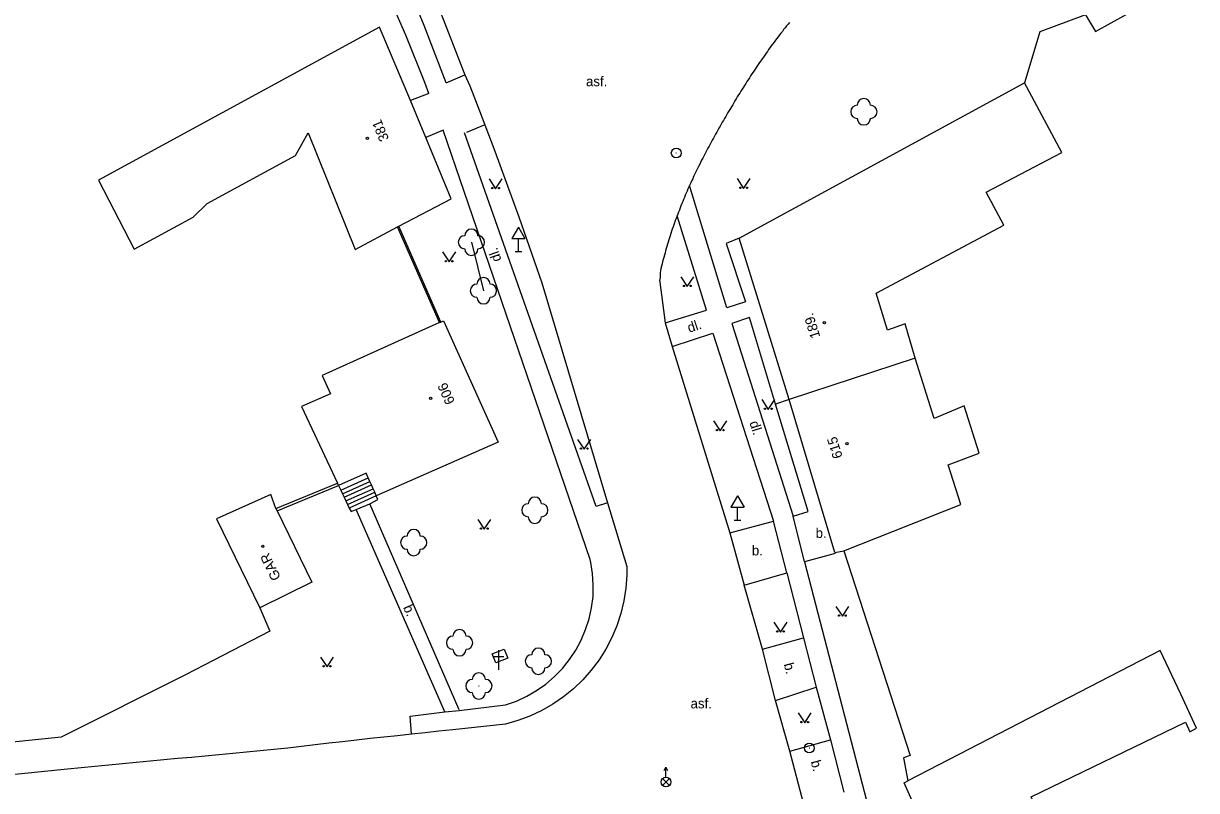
# Model space of a CAD drawing. Extents: x -545714 to -535419, y -1201788 to -1194297.
# Drawn here: x -535590.1 to -535501, y -1201602.5 to -1201544.3 of the extents above; entities that cross this region are included whole.
import ezdxf

# ---------------------------------------------------------------- set-up
doc = ezdxf.new("R2010")
doc.units = 0
for name, color, linetype in [('Vrstva 1', 7, 'Continuous'), ('Vrstva 10', 7, 'Continuous'), ('Vrstva 11', 7, 'Continuous'), ('Vrstva 12', 7, 'Continuous'), ('Vrstva 15', 7, 'Continuous'), ('Vrstva 2', 7, 'Continuous'), ('Vrstva 3', 7, 'Continuous'), ('Vrstva 4', 7, 'Continuous'), ('Vrstva 5', 7, 'Continuous'), ('Vrstva 8', 7, 'Continuous'), ('Vrstva 9', 7, 'Continuous')]:
    doc.layers.add(name, color=color, linetype=linetype)

msp = doc.modelspace()

# ---------------------------------------------------------------- linework, layer by layer
at = {"layer": 'Vrstva 1'}
for centre, radius in [((-535540.49, -1201554.1), 0.375), ((-535540.49, -1201554.1), 0.0005), ((-535530.38, -1201599.301), 0.375), ((-535530.38, -1201599.301), 0.0005)]:
    msp.add_circle(centre, radius, dxfattribs=at)
at = {"layer": 'Vrstva 10'}
for p, q in [((-535552.48, -1201559.724), (-535552.98, -1201560.59)), ((-535552.48, -1201559.724), (-535551.98, -1201560.59)), ((-535552.98, -1201560.59), (-535551.98, -1201560.59)), ((-535552.48, -1201561.59), (-535552.48, -1201560.59)), ((-535552.73, -1201561.59), (-535552.23, -1201561.59)), ((-535535.84, -1201580.134), (-535536.34, -1201581)), ((-535535.84, -1201580.134), (-535535.34, -1201581)), ((-535536.34, -1201581), (-535535.34, -1201581)), ((-535535.84, -1201582), (-535535.84, -1201581)), ((-535536.09, -1201582), (-535535.59, -1201582))]:
    msp.add_line(p, q, dxfattribs=at)
for points in [[(-535509.4, -1201543.6), (-535512.88, -1201544.9), (-535514.03, -1201548.76)], [(-535558.47, -1201566.98), (-535561.66, -1201559.7)], [(-535558.38, -1201566.94), (-535561.57, -1201559.65)], [(-535570.89, -1201581.11), (-535566.22, -1201579.17)], [(-535570.81, -1201581.28), (-535566.14, -1201579.35)], [(-535527.76, -1201584.32), (-535522.72, -1201599.86), (-535523.22, -1201600.05), (-535522.9, -1201601.79)], [(-535572.12, -1201588.65), (-535571.35, -1201590.42), (-535577.76, -1201593.75), (-535587.2, -1201598.48), (-535604.18, -1201600.22)]]:
    msp.add_lwpolyline(points, dxfattribs=at)
at = {"layer": 'Vrstva 11'}
for points in [[(-535559.28, -1201549.57), (-535559.59, -1201548.75), (-535561.04, -1201545.16), (-535567.24, -1201530.99), (-535567.78, -1201529.85), (-535568.21, -1201528.88), (-535572, -1201520.91), (-535578.88, -1201508.46), (-535580.82, -1201505.2), (-535588.58, -1201492.55)], [(-535566.65, -1201524.99), (-535563.37, -1201531.99), (-535558.46, -1201543.26), (-535558.14, -1201544.05), (-535556.54, -1201548.16)], [(-535557.96, -1201548.78), (-535558.09, -1201548.43), (-535559.64, -1201544.42), (-535559.94, -1201543.67), (-535565.46, -1201531.02), (-535568.06, -1201525.62)], [(-535531.89, -1201544.19), (-535532, -1201544.32), (-535532.11, -1201544.45), (-535532.22, -1201544.59), (-535532.33, -1201544.72), (-535532.43, -1201544.86), (-535532.54, -1201544.99), (-535532.65, -1201545.13), (-535532.75, -1201545.27), (-535532.86, -1201545.4), (-535532.96, -1201545.54), (-535533.06, -1201545.68), (-535533.17, -1201545.82), (-535533.27, -1201545.96), (-535533.37, -1201546.1), (-535533.47, -1201546.24), (-535533.57, -1201546.38), (-535533.67, -1201546.52), (-535533.77, -1201546.67), (-535533.87, -1201546.81), (-535533.97, -1201546.95), (-535534.07, -1201547.09), (-535534.16, -1201547.23), (-535534.26, -1201547.38), (-535534.36, -1201547.52), (-535534.45, -1201547.66), (-535534.55, -1201547.81), (-535534.65, -1201547.95), (-535534.74, -1201548.09), (-535534.84, -1201548.24), (-535534.93, -1201548.38), (-535535.02, -1201548.53), (-535535.12, -1201548.67), (-535535.21, -1201548.82), (-535535.3, -1201548.96), (-535535.39, -1201549.11), (-535535.49, -1201549.25), (-535535.58, -1201549.4), (-535535.67, -1201549.55), (-535535.76, -1201549.69)], [(-535557.96, -1201548.78), (-535556.54, -1201548.16)], [(-535556.54, -1201548.16), (-535556.17, -1201548.99), (-535555.44, -1201550.89)], [(-535559.28, -1201549.57), (-535560.67, -1201550.12)], [(-535535.76, -1201549.69), (-535535.85, -1201549.84), (-535535.94, -1201549.99), (-535536.03, -1201550.14), (-535536.12, -1201550.28), (-535536.2, -1201550.43), (-535536.29, -1201550.58), (-535536.38, -1201550.73), (-535536.47, -1201550.88), (-535536.56, -1201551.02), (-535536.64, -1201551.17), (-535536.73, -1201551.32), (-535536.82, -1201551.47), (-535536.9, -1201551.62), (-535536.99, -1201551.77), (-535537.07, -1201551.92), (-535537.16, -1201552.07), (-535537.25, -1201552.22), (-535537.33, -1201552.37), (-535537.41, -1201552.52), (-535537.5, -1201552.67), (-535537.58, -1201552.83), (-535537.67, -1201552.98), (-535537.75, -1201553.13), (-535537.83, -1201553.28), (-535537.91, -1201553.43), (-535538, -1201553.58), (-535538.08, -1201553.74), (-535538.16, -1201553.89), (-535538.24, -1201554.04), (-535538.32, -1201554.19), (-535538.4, -1201554.35), (-535538.48, -1201554.5), (-535538.56, -1201554.65), (-535538.64, -1201554.81), (-535538.71, -1201554.96), (-535538.79, -1201555.12), (-535538.87, -1201555.27), (-535538.94, -1201555.42), (-535539.02, -1201555.58), (-535539.09, -1201555.73), (-535539.17, -1201555.89), (-535539.24, -1201556.05), (-535539.31, -1201556.2), (-535539.39, -1201556.36), (-535539.46, -1201556.51), (-535539.49, -1201556.58)], [(-535555.44, -1201550.89), (-535555.04, -1201551.97)], [(-535555.04, -1201551.97), (-535556.43, -1201552.53)], [(-535555.04, -1201551.97), (-535554.27, -1201553.96), (-535552.45, -1201558.95), (-535550.71, -1201563.97), (-535545.7, -1201580.68)], [(-535558.19, -1201552.37), (-535559.5, -1201552.92)], [(-535556.97, -1201596.44), (-535553.45, -1201596.02), (-535552.63, -1201595.73), (-535551.85, -1201595.37), (-535551.1, -1201594.94), (-535550.39, -1201594.44), (-535549.74, -1201593.88), (-535549.13, -1201593.26), (-535548.59, -1201592.58), (-535548.11, -1201591.86), (-535547.7, -1201591.1), (-535547.37, -1201590.31), (-535547.11, -1201589.48), (-535546.92, -1201588.64), (-535546.81, -1201587.78), (-535546.79, -1201586.91), (-535546.84, -1201586.05), (-535546.98, -1201585.2), (-535547.02, -1201584.99), (-535558.19, -1201552.37)], [(-535545.7, -1201580.68), (-535546.57, -1201580.96), (-535556.56, -1201552.58)], [(-535539.49, -1201556.58), (-535539.53, -1201556.67), (-535539.6, -1201556.83), (-535539.67, -1201556.99), (-535539.74, -1201557.15), (-535539.81, -1201557.31), (-535539.87, -1201557.47), (-535539.94, -1201557.62), (-535540, -1201557.78), (-535540.07, -1201557.94), (-535540.13, -1201558.11), (-535540.19, -1201558.26), (-535540.25, -1201558.43), (-535540.31, -1201558.59), (-535540.38, -1201558.75), (-535540.43, -1201558.87)], [(-535536.64, -1201565.86), (-535539.49, -1201556.58)], [(-535540.43, -1201558.87), (-535540.5, -1201559.07), (-535540.56, -1201559.24), (-535540.62, -1201559.4), (-535540.67, -1201559.56), (-535540.73, -1201559.72), (-535540.79, -1201559.89), (-535540.84, -1201560.05), (-535540.89, -1201560.21), (-535540.95, -1201560.38), (-535541, -1201560.54), (-535541.05, -1201560.7), (-535541.1, -1201560.87), (-535541.15, -1201561.03), (-535541.2, -1201561.2), (-535541.25, -1201561.36), (-535541.3, -1201561.53), (-535541.34, -1201561.69), (-535541.39, -1201561.86), (-535541.44, -1201562.03), (-535541.48, -1201562.19), (-535541.53, -1201562.36), (-535541.57, -1201562.53), (-535541.61, -1201562.7), (-535541.66, -1201562.87), (-535541.69, -1201563.04), (-535541.71, -1201563.21), (-535541.72, -1201563.39), (-535541.72, -1201563.56), (-535541.75, -1201563.79), (-535541.73, -1201563.91)], [(-535538.2, -1201566.04), (-535540.43, -1201558.87)], [(-535535.71, -1201560.57), (-535536.7, -1201560.97), (-535535.22, -1201565.41), (-535536.64, -1201565.86)], [(-535541.73, -1201563.91), (-535541.33, -1201567.01)], [(-535541.33, -1201567.01), (-535538.2, -1201566.04)], [(-535541.33, -1201567.01), (-535540.8, -1201568.81)], [(-535532.94, -1201573.19), (-535534.92, -1201566.59), (-535536.26, -1201567.04), (-535531.61, -1201581.69)], [(-535540.8, -1201568.81), (-535537.7, -1201567.79)], [(-535537.7, -1201567.79), (-535533.09, -1201582.08)], [(-535540.8, -1201568.81), (-535536.43, -1201582.96)], [(-535531.9, -1201572.83), (-535532.94, -1201573.19)], [(-535531.61, -1201581.69), (-535530.48, -1201581.33), (-535532.94, -1201573.19)], [(-535565.97, -1201579.71), (-535563.88, -1201578.78)], [(-535566.14, -1201579.35), (-535565.97, -1201579.71)], [(-535565.97, -1201579.71), (-535565.84, -1201579.98)], [(-535565.84, -1201579.98), (-535563.76, -1201579.05)], [(-535565.71, -1201580.25), (-535563.64, -1201579.32)], [(-535565.58, -1201580.52), (-535563.51, -1201579.6)], [(-535565.84, -1201579.98), (-535565.71, -1201580.25)], [(-535565.71, -1201580.25), (-535565.58, -1201580.52)], [(-535565.58, -1201580.52), (-535565.45, -1201580.8)], [(-535565.45, -1201580.8), (-535563.39, -1201579.87)], [(-535563.27, -1201580.14), (-535565.32, -1201581.07)], [(-535565.32, -1201581.07), (-535565.19, -1201581.34), (-535564.79, -1201581.19), (-535563.76, -1201580.74), (-535563.15, -1201580.42), (-535563.27, -1201580.14)], [(-535556.98, -1201596.39), (-535563.76, -1201580.74)], [(-535545.7, -1201580.68), (-535544.25, -1201585.52), (-535544.25, -1201586.18), (-535544.32, -1201587.16), (-535544.47, -1201588.13), (-535544.7, -1201589.08), (-535545, -1201590.01), (-535545.38, -1201590.91), (-535545.83, -1201591.78), (-535546.35, -1201592.61), (-535546.94, -1201593.39), (-535547.59, -1201594.13), (-535548.3, -1201594.8), (-535549.06, -1201595.42), (-535549.86, -1201595.97), (-535550.71, -1201596.46), (-535551.6, -1201596.87), (-535552.52, -1201597.22), (-535553.46, -1201597.48), (-535557.47, -1201597.91), (-535558.52, -1201598.03), (-535559.56, -1201598.14), (-535560.61, -1201598.25)], [(-535565.45, -1201580.8), (-535565.32, -1201581.07)], [(-535558.07, -1201596.56), (-535564.79, -1201581.19)], [(-535536.43, -1201582.96), (-535533.09, -1201582.08)], [(-535532.08, -1201585.99), (-535533.09, -1201582.08)], [(-535530.74, -1201585.15), (-535531.61, -1201581.69)], [(-535536.43, -1201582.96), (-535535.33, -1201586.94)], [(-535528.42, -1201584.52), (-535530.74, -1201585.15)], [(-535530.74, -1201585.15), (-535525.02, -1201607.19), (-535521.43, -1201605.87)], [(-535535.33, -1201586.94), (-535532.08, -1201585.99)], [(-535532.08, -1201585.99), (-535530.82, -1201590.92)], [(-535533.95, -1201591.78), (-535535.33, -1201586.94)], [(-535533.95, -1201591.78), (-535530.82, -1201590.92)], [(-535530.82, -1201590.92), (-535529.85, -1201594.69)], [(-535554.19, -1201592.84), (-535554.46, -1201592.14), (-535553.56, -1201591.78), (-535553.29, -1201592.48), (-535554.19, -1201592.84)], [(-535532.94, -1201595.69), (-535533.95, -1201591.78)], [(-535532.94, -1201595.69), (-535529.85, -1201594.69)], [(-535529.85, -1201594.69), (-535528.76, -1201598.67)], [(-535531.87, -1201599.53), (-535532.94, -1201595.69)], [(-535560.61, -1201598.25), (-535560.69, -1201596.89), (-535558.07, -1201596.56)], [(-535558.07, -1201596.56), (-535556.97, -1201596.44)], [(-535560.61, -1201598.25), (-535561.65, -1201598.37), (-535562.7, -1201598.48), (-535563.74, -1201598.59), (-535564.78, -1201598.7), (-535565.83, -1201598.82), (-535566.87, -1201598.93), (-535567.92, -1201599.06), (-535568.96, -1201599.19), (-535570, -1201599.31), (-535571.05, -1201599.42), (-535572.09, -1201599.51), (-535573.14, -1201599.62), (-535574.18, -1201599.72), (-535575.23, -1201599.81), (-535576.27, -1201599.91), (-535577.32, -1201600.01), (-535578.37, -1201600.11), (-535579.41, -1201600.21), (-535580.46, -1201600.31), (-535581.5, -1201600.41), (-535582.55, -1201600.51), (-535583.59, -1201600.61), (-535584.64, -1201600.71), (-535585.68, -1201600.81), (-535586.73, -1201600.91), (-535601.96, -1201602.45)], [(-535531.87, -1201599.53), (-535528.76, -1201598.67)], [(-535528.76, -1201598.67), (-535527.76, -1201602.65)], [(-535530.83, -1201603.48), (-535531.87, -1201599.53)]]:
    msp.add_lwpolyline(points, dxfattribs=at)
at = {"layer": 'Vrstva 12'}
msp.add_lwpolyline([(-535556.05, -1201560.88), (-535555.13, -1201564.56)], dxfattribs=at)
for centre in [(-535526.24, -1201550.97), (-535556.05, -1201560.88), (-535555.13, -1201564.56), (-535551.23, -1201581.24), (-535560.43, -1201583.7), (-535556.95, -1201591.3), (-535550.96, -1201592.71), (-535555.48, -1201594.59)]:
    msp.add_circle(centre, 0.0005, dxfattribs=at)
for centre, start, end in [((-535526.24, -1201550.47), 0, 179.99999), ((-535526.74, -1201550.97), 89.99999, 269.99999), ((-535525.74, -1201550.97), 270, 89.99999), ((-535526.24, -1201551.47), 179.99999, 359.99999), ((-535556.05, -1201560.38), 0, 179.99999), ((-535556.55, -1201560.88), 89.99999, 269.99999), ((-535555.55, -1201560.88), 270, 89.99999), ((-535556.05, -1201561.38), 179.99999, 359.99999), ((-535555.13, -1201564.06), 0, 179.99999), ((-535555.63, -1201564.56), 89.99999, 269.99999), ((-535554.63, -1201564.56), 270, 89.99999), ((-535555.13, -1201565.06), 179.99999, 359.99999), ((-535551.73, -1201581.24), 89.99999, 269.99999), ((-535551.23, -1201580.74), 0, 179.99999), ((-535550.73, -1201581.24), 270, 89.99999), ((-535551.23, -1201581.74), 179.99999, 359.99999), ((-535560.93, -1201583.7), 89.99999, 269.99999), ((-535560.43, -1201583.2), 0, 179.99999), ((-535559.93, -1201583.7), 270, 89.99999), ((-535560.43, -1201584.2), 179.99999, 359.99999), ((-535556.95, -1201590.8), 0, 179.99999), ((-535557.45, -1201591.3), 89.99999, 269.99999), ((-535556.45, -1201591.3), 270, 89.99999), ((-535556.95, -1201591.8), 179.99999, 359.99999), ((-535551.46, -1201592.71), 89.99999, 269.99999), ((-535550.96, -1201592.21), 0, 179.99999), ((-535550.46, -1201592.71), 270, 89.99999), ((-535550.96, -1201593.21), 179.99999, 359.99999), ((-535555.98, -1201594.59), 89.99999, 269.99999), ((-535555.48, -1201594.09), 0, 179.99999), ((-535554.98, -1201594.59), 270, 89.99999), ((-535555.48, -1201595.09), 179.99999, 359.99999)]:
    msp.add_arc(centre, 0.5, start, end, dxfattribs=at)
at = {"layer": 'Vrstva 2'}
for p, q in [((-535541.27, -1201601.505), (-535541.27, -1201600.755)), ((-535541.535, -1201602.144), (-535541.006, -1201601.616)), ((-535541.006, -1201602.148), (-535541.535, -1201601.616))]:
    msp.add_line(p, q, dxfattribs=at)
msp.add_lwpolyline([(-535541.395, -1201601.005), (-535541.27, -1201600.755), (-535541.145, -1201601.005)], dxfattribs=at)
msp.add_circle((-535541.27, -1201601.88), 0.375, dxfattribs=at)
at = {"layer": 'Vrstva 3'}
for points in [[(-535554.71, -1201556.06), (-535554.21, -1201556.81), (-535553.71, -1201556.06)], [(-535535.87, -1201556.04), (-535535.37, -1201556.79), (-535534.87, -1201556.04)], [(-535558.24, -1201561.62), (-535557.74, -1201562.37), (-535557.24, -1201561.62)], [(-535540.15, -1201563.5), (-535539.65, -1201564.25), (-535539.15, -1201563.5)], [(-535534, -1201572.83), (-535533.5, -1201573.58), (-535533, -1201572.83)], [(-535537.65, -1201574.45), (-535537.15, -1201575.2), (-535536.65, -1201574.45)], [(-535547.98, -1201575.86), (-535547.48, -1201576.61), (-535546.98, -1201575.86)], [(-535555.57, -1201581.93), (-535555.07, -1201582.68), (-535554.57, -1201581.93)], [(-535528.37, -1201588.54), (-535527.87, -1201589.29), (-535527.37, -1201588.54)], [(-535533.07, -1201589.74), (-535532.57, -1201590.49), (-535532.07, -1201589.74)], [(-535567.51, -1201592.39), (-535567.01, -1201593.14), (-535566.51, -1201592.39)], [(-535531.23, -1201596.63), (-535530.73, -1201597.38), (-535530.23, -1201596.63)]]:
    msp.add_lwpolyline(points, dxfattribs=at)
for centre in [(-535535.62, -1201556.74), (-535535.12, -1201556.74), (-535554.46, -1201556.76), (-535553.96, -1201556.76), (-535557.99, -1201562.32), (-535557.49, -1201562.32), (-535539.9, -1201564.2), (-535539.4, -1201564.2), (-535533.75, -1201573.53), (-535533.25, -1201573.53), (-535537.4, -1201575.15), (-535536.9, -1201575.15), (-535547.73, -1201576.56), (-535547.23, -1201576.56), (-535555.32, -1201582.63), (-535554.82, -1201582.63), (-535528.12, -1201589.24), (-535527.62, -1201589.24), (-535532.82, -1201590.44), (-535532.32, -1201590.44), (-535567.26, -1201593.09), (-535566.76, -1201593.09), (-535530.98, -1201597.33), (-535530.48, -1201597.33)]:
    msp.add_circle(centre, 0.05, dxfattribs=at)
at = {"layer": 'Vrstva 4'}
for points in [[(-535561.57, -1201559.65), (-535557.59, -1201557.59), (-535559.5, -1201552.92), (-535560.67, -1201550.12), (-535563.03, -1201544.54)], [(-535535.71, -1201560.57), (-535514.03, -1201548.76)], [(-535561.66, -1201559.7), (-535561.57, -1201559.65)], [(-535531.9, -1201572.83), (-535535.71, -1201560.57)], [(-535558.38, -1201566.94), (-535558.16, -1201566.84), (-535554.01, -1201576.07), (-535563.27, -1201580.14)], [(-535558.47, -1201566.98), (-535558.38, -1201566.94)], [(-535528.44, -1201584.45), (-535531.9, -1201572.83)], [(-535563.88, -1201578.78), (-535564.05, -1201578.41), (-535566.14, -1201579.35)], [(-535563.76, -1201579.05), (-535563.88, -1201578.78)], [(-535566.14, -1201579.35), (-535566.22, -1201579.17)], [(-535563.64, -1201579.32), (-535563.76, -1201579.05)], [(-535563.51, -1201579.6), (-535563.64, -1201579.32)], [(-535563.39, -1201579.87), (-535563.51, -1201579.6)], [(-535563.27, -1201580.14), (-535563.39, -1201579.87)], [(-535570.81, -1201581.28), (-535568.17, -1201586.7), (-535572.12, -1201588.65)], [(-535570.89, -1201581.11), (-535570.81, -1201581.28)], [(-535528.44, -1201584.45), (-535527.76, -1201584.32)], [(-535523.18, -1201601.94), (-535522.9, -1201601.79)], [(-535516.38, -1201617.2), (-535521.06, -1201606.7), (-535521.43, -1201605.87), (-535523.18, -1201601.94)]]:
    msp.add_lwpolyline(points, dxfattribs=at)
at = {"layer": 'Vrstva 5'}
for points in [[(-535509.4, -1201543.6), (-535508.65, -1201544.87), (-535506.27, -1201543.55), (-535509.62, -1201537.58)], [(-535563.03, -1201544.54), (-535584.37, -1201556.16), (-535581.66, -1201561.4), (-535577.17, -1201558.97), (-535576.12, -1201557.94), (-535569.4, -1201554.28), (-535568.45, -1201552.56), (-535564.87, -1201561.42), (-535561.66, -1201559.7)], [(-535522.34, -1201569.68), (-535523.11, -1201567.09), (-535524.44, -1201567.55), (-535525.31, -1201564.75), (-535515.61, -1201559.58), (-535516.95, -1201557.07), (-535511.2, -1201554.06), (-535514.03, -1201548.76)], [(-535558.47, -1201566.98), (-535567.38, -1201570.99), (-535566.75, -1201572.4), (-535568.96, -1201573.36), (-535566.22, -1201579.17)], [(-535527.76, -1201584.32), (-535518.87, -1201580.79), (-535519.83, -1201577.8), (-535517.48, -1201576.9), (-535518.61, -1201573.3), (-535520.9, -1201574.27), (-535522.34, -1201569.68), (-535531.9, -1201572.83)], [(-535570.89, -1201581.11), (-535571.29, -1201580.05), (-535575.42, -1201581.9), (-535572.12, -1201588.65)], [(-535511.42, -1201615.11), (-535512.76, -1201611.86), (-535510.13, -1201610.73), (-535513.53, -1201603.02), (-535501.82, -1201597.33), (-535501.47, -1201598.07), (-535500.97, -1201597.79), (-535502.17, -1201595.2), (-535503.72, -1201591.89), (-535522.9, -1201601.79)]]:
    msp.add_lwpolyline(points, dxfattribs=at)
at = {"layer": 'Vrstva 9'}
for p, q in [((-535553.96, -1201593.36), (-535553.96, -1201591.86)), ((-535554.335, -1201592.36), (-535553.585, -1201592.36))]:
    msp.add_line(p, q, dxfattribs=at)
for centre in [(-535563.95, -1201552.98), (-535529.23, -1201566.99), (-535559.15, -1201572.74), (-535527.52, -1201576.19), (-535571.89, -1201583.98)]:
    msp.add_circle(centre, 0.0875, dxfattribs=at)

# ---------------------------------------------------------------- texts
at = {"layer": 'Vrstva 15'}
for s, p in [('asf.', (-535547.34, -1201549.03)), ('b.', (-535529.9, -1201583.34)), ('b.', (-535534.74, -1201584.67)), ('asf.', (-535539.4, -1201596.29))]:
    msp.add_text(s, height=0.75, dxfattribs=at).set_placement(p)
for s, rotation, p in [('dl.', 109.36, (-535553.75, -1201562.22)), ('dl.', 18.20997, (-535539.5, -1201567.76)), ('dl.', 287.88001, (-535534.94, -1201574.58)), ('GAR', 115.92999, (-535570.5, -1201586.36)), ('b.', 293.62001, (-535561.25, -1201588.61)), ('b.', 284.48002, (-535532.33, -1201592.93)), ('b.', 284.75, (-535530.28, -1201600.33))]:
    msp.add_text(s, height=0.75, rotation=rotation, dxfattribs=at).set_placement(p)
at = {"layer": 'Vrstva 8'}
for s, rotation, p in [('381', 112.58002, (-535562.29, -1201553.03)), ('189.', 107.40002, (-535529.54, -1201568.05)), ('606', 114.16998, (-535557.28, -1201573)), ('615', 107.27002, (-535527.84, -1201577.18))]:
    msp.add_text(s, height=0.75, rotation=rotation, dxfattribs=at).set_placement(p)

doc.saveas('drawing.dxf')
